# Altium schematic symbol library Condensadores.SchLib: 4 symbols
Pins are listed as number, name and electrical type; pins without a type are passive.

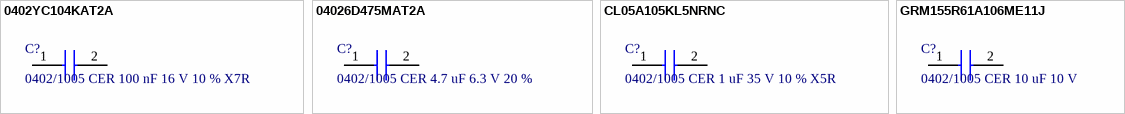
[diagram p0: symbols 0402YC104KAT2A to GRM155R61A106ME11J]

## 0402YC104KAT2A
designator C?, comment 0402/1005 CER 100 nF 16 V 10 % X7R
0402/1005 CER nF 100 16 V 10 % X7R; Manufacturer_Name: Kyocera AVX; Manufacturer_Part_Number: 0402YC104KAT2A; Description: Multilayer Ceramic Capacitor, 0.1 uF, 16 V, ï¿½ 10%, X7R, 0402 [1005 Metric]; Dielectric Material: Ceramic; Material: 4241ConductorMaterial; Tolerance: 10%; Value: 100nF; Voltage Rating: 16V
footprint CAPC1005X56N
pins: 1, 2

## 04026D475MAT2A
designator C?, comment 0402/1005 CER 4.7 uF 6.3 V 20 %
0402/1005 CER uF 4.7 6.3 V 20 %; Manufacturer_Name: Kyocera AVX; Manufacturer_Part_Number: 04026D475MAT2A; Description: 0402 4.7 uF 6.3 V ±20 % Tolerance X5R Surface Mount Multilayer Ceramic Capacitor; Material: 4241ConductorMaterial; Voltage Rating (DC): 6.3V
footprint CAPC1005X56N
pins: 1, 2

## CL05A105KL5NRNC
designator C?, comment 0402/1005 CER 1 uF 35 V 10 % X5R
0402/1005 CER uF 1 35 V 10 % X5R; Manufacturer_Name: SAMSUNG; Manufacturer_Part_Number: CL05A105KL5NRNC; Description: Ceramic Capacitor, Multilayer, Ceramic, 35V, 10% +Tol, 10% -Tol, X5R, 15% TC, 1uF, Surface Mount, 0402; Material: 4241ConductorMaterial; Value: 1uF; Voltage Rating: 35V; Tolerance: 10%
footprint CAPC1005X65N
pins: 1, 2

## GRM155R61A106ME11J
designator C?, comment 0402/1005 CER 10 uF 10 V
0402/1005 CER uF 10 10 V; Manufacturer_Name: Murata Electronics; Manufacturer_Part_Number: GRM155R61A106ME11J; Manufacturer: Murata; Description: Multilayer Ceramic Capacitors MLCC - SMD/SMTSimulate & compare characteristics in SimSurfing; Material: 4241ConductorMaterial; Value: 10uF; Dielectric: 1537DielectricType; Tolerance: 20%; Voltage Rating: 10V
footprint GRM15x
pins: 1, 2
